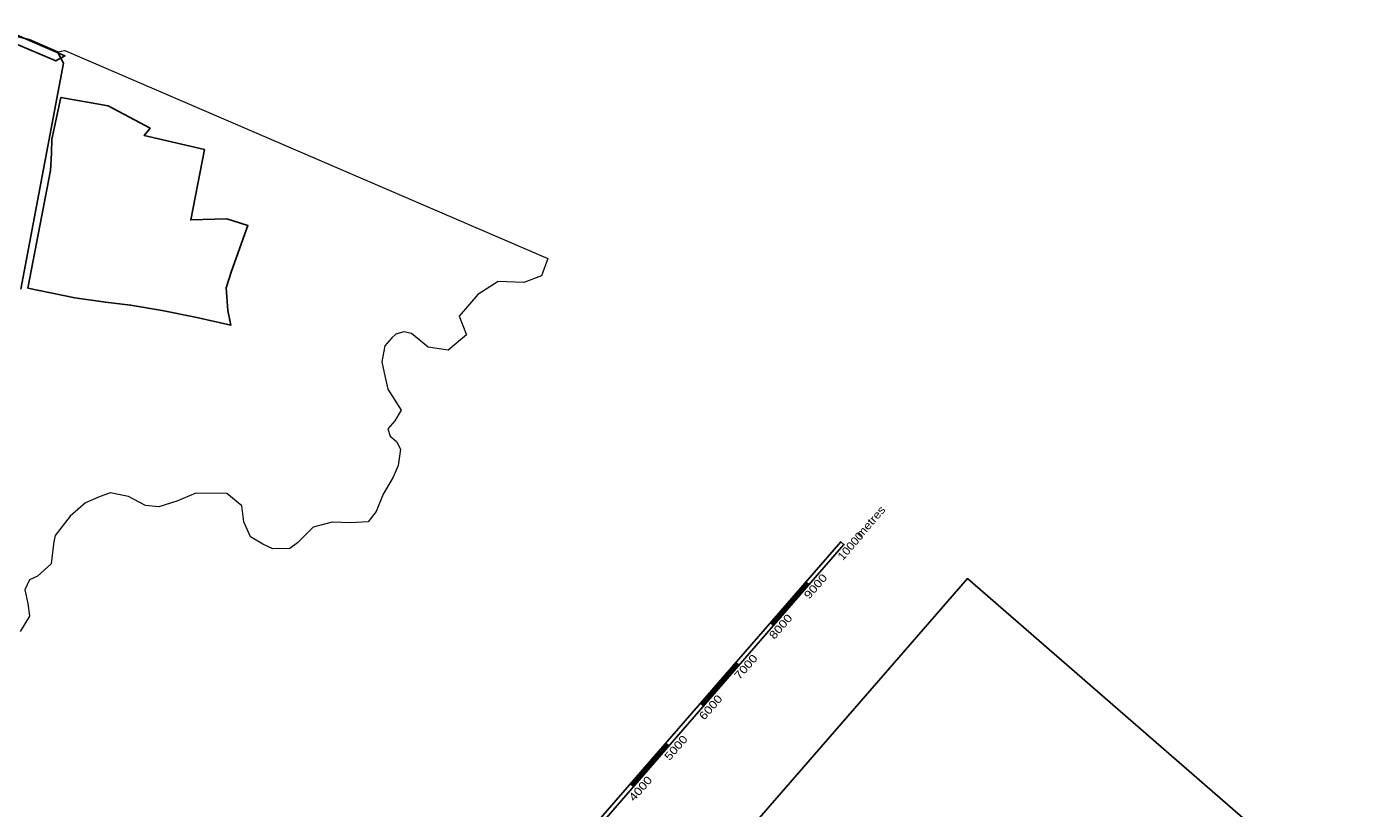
# Model space of a CAD drawing. Extents: x 290038 to 370218, y 2722677 to 2808586.
# Drawn here: x 345284 to 370218, y 2781010 to 2795659 of the extents above; entities that cross this region are included whole.
import ezdxf
from ezdxf.enums import TextEntityAlignment as Align

# ---------------------------------------------------------------- set-up
doc = ezdxf.new("R2010")
doc.units = 0
doc.header["$LTSCALE"] = 88
for name, color, linetype, lineweight in [('20', 7, 'Continuous', 13), ('21', 7, 'Continuous', 25), ('26', 7, 'Continuous', 13), ('63', 7, 'Continuous', 35)]:
    doc.layers.add(name, color=color, linetype=linetype, lineweight=lineweight)

msp = doc.modelspace()

# ---------------------------------------------------------------- linework, layer by layer
at = {"layer": '20', "lineweight": 25}
msp.add_lwpolyline([(313980.4, 2729027.31), (362912.77, 2785317.56), (370218.38, 2778966.9), (321286.01, 2722676.64)], close=True, dxfattribs=at)
at = {"layer": '21'}
msp.add_lwpolyline([(344750.9, 2795557.88), (345329.48, 2795416.12), (345865.2, 2795185.51), (345973.25, 2794976.23), (345177.76, 2790737.42)], dxfattribs=at)
msp.add_lwpolyline([(345304.18, 2790758.67), (345729.85, 2792965.81), (345749.89, 2793288.43), (345754.27, 2793553.08), (345928.31, 2794332.44), (346812.99, 2794171.89), (347598.53, 2793757.49), (347488.87, 2793617.23), (348618.94, 2793353.68), (348361.15, 2792038.63), (349038.19, 2792058.59), (349431.28, 2791931.64), (349120.21, 2791074.54), (349024.14, 2790764.32), (349056.62, 2790342.35), (349109.52, 2790063.71), (348470.63, 2790207.45), (347822.88, 2790341), (347233.43, 2790441.77), (346759.56, 2790495.76), (346189.89, 2790579.34)], close=True, dxfattribs=at)
at = {"layer": '26', "lineweight": 25}
msp.add_lwpolyline([(344723.38, 2795659.4), (346002.04, 2795110.61), (345829.19, 2795017.45), (345037.34, 2795358.32), (344889.26, 2795420.15), (344735.09, 2795470.7), (344699.18, 2795527.53)], close=True, dxfattribs=at)
at = {"layer": '26'}
msp.add_lwpolyline([(345177.76, 2790737.42), (345973.25, 2794976.23), (345865.2, 2795185.51), (345999.51, 2795210.65), (355047.94, 2791315.46), (354934.05, 2790991.89), (354599.89, 2790862.82), (354117.14, 2790881.99), (353739.04, 2790638.55), (353389.67, 2790236.65), (353529.22, 2789886.5), (353183.83, 2789595.56), (352809.31, 2789654.13), (352494.33, 2789908.87), (352352.3, 2789936.98), (352204.11, 2789894.17), (352127.47, 2789827.3), (351995.28, 2789675.22), (351941.21, 2789378.96), (351982.65, 2789171.3), (352049.54, 2788865.23), (352301.7, 2788474.4), (352182.23, 2788273.13), (352050.04, 2788121.06), (352097.65, 2787984.32), (352213.54, 2787883.58), (352291.66, 2787739.38), (352248.13, 2787433.96), (352149.72, 2787214.37), (351966.34, 2786897.02), (351833.45, 2786573.92), (351683.47, 2786380.1), (351353.28, 2786362), (351011.47, 2786373.08), (350655.14, 2786282.35), (350360.24, 2785985.66), (350215.32, 2785882.79), (349894.58, 2785875.55), (349709.31, 2785960.32), (349480.81, 2786101.75), (349355.08, 2786382.68), (349318.7, 2786681.29), (349035.33, 2786908.54), (348452.68, 2786919.2), (348099.64, 2786768.4), (347764.38, 2786659.36), (347511.92, 2786688.11), (347191.88, 2786851.9), (346846.78, 2786923.04), (346630.3, 2786844.24), (346385.5, 2786732.85), (346097.85, 2786487.06), (345816.77, 2786121.15), (345792.81, 2786008.48), (345745.3, 2785592.09), (345487.07, 2785358.88), (345339.97, 2785296.05), (345249.92, 2785107.34), (345304.09, 2784850.48), (345337.19, 2784611.93), (345162.15, 2784325.46)], dxfattribs=at)
at = {"layer": '63', "lineweight": 25}
for p, q in [((353321.51, 2777702.6), (360538.16, 2786004.41)), ((353381.89, 2777650.12), (360598.54, 2785951.92)), ((360606.08, 2785945.36), (360530.61, 2786010.97))]:
    msp.add_line(p, q, dxfattribs=at)
at = {"layer": '63'}
for p, q in [((359237.44, 2784485.09), (359893.5, 2785239.8)), ((359237.81, 2784484.76), (359893.87, 2785239.47)), ((359238.19, 2784484.43), (359894.25, 2785239.14)), ((359238.57, 2784484.1), (359894.63, 2785238.81)), ((359238.95, 2784483.78), (359895, 2785238.48)), ((359239.32, 2784483.45), (359895.38, 2785238.16)), ((359239.7, 2784483.12), (359895.76, 2785237.83)), ((359240.08, 2784482.79), (359896.14, 2785237.5)), ((359240.45, 2784482.46), (359896.51, 2785237.17)), ((359240.83, 2784482.14), (359896.89, 2785236.84)), ((359241.21, 2784481.81), (359897.27, 2785236.52)), ((359241.59, 2784481.48), (359897.65, 2785236.19)), ((359241.97, 2784481.15), (359898.02, 2785235.86)), ((359242.34, 2784480.82), (359898.4, 2785235.53)), ((359242.72, 2784480.5), (359898.78, 2785235.21)), ((359243.1, 2784480.17), (359899.15, 2785234.88)), ((359243.47, 2784479.84), (359899.53, 2785234.55)), ((359243.85, 2784479.51), (359899.91, 2785234.22)), ((359244.23, 2784479.18), (359900.29, 2785233.89)), ((359244.61, 2784478.86), (359900.67, 2785233.56)), ((359244.98, 2784478.53), (359901.04, 2785233.24)), ((359245.36, 2784478.2), (359901.42, 2785232.91)), ((359245.74, 2784477.87), (359901.8, 2785232.58)), ((359246.12, 2784477.54), (359902.17, 2785232.25)), ((359246.49, 2784477.21), (359902.55, 2785231.92)), ((359246.87, 2784476.89), (359902.93, 2785231.6)), ((359247.25, 2784476.56), (359903.31, 2785231.27)), ((359247.62, 2784476.23), (359903.68, 2785230.94)), ((359248, 2784475.9), (359904.06, 2785230.61)), ((359248.38, 2784475.58), (359904.44, 2785230.29)), ((359248.76, 2784475.25), (359904.82, 2785229.96)), ((359249.13, 2784474.92), (359905.19, 2785229.63)), ((359249.51, 2784474.59), (359905.57, 2785229.3)), ((359249.89, 2784474.26), (359905.95, 2785228.97)), ((359250.27, 2784473.94), (359906.32, 2785228.64)), ((359250.64, 2784473.61), (359906.7, 2785228.32)), ((359251.02, 2784473.28), (359907.08, 2785227.99)), ((359251.4, 2784472.95), (359907.46, 2785227.66)), ((359251.78, 2784472.62), (359907.83, 2785227.33)), ((359252.15, 2784472.29), (359908.21, 2785227)), ((359252.53, 2784471.97), (359908.59, 2785226.68)), ((359252.91, 2784471.64), (359908.97, 2785226.35)), ((359253.29, 2784471.31), (359909.34, 2785226.02)), ((359253.66, 2784470.98), (359909.72, 2785225.69)), ((359254.04, 2784470.65), (359910.1, 2785225.36)), ((359254.42, 2784470.33), (359910.48, 2785225.04)), ((359254.79, 2784470), (359910.85, 2785224.71)), ((359255.17, 2784469.67), (359911.23, 2785224.38)), ((359255.55, 2784469.34), (359911.61, 2785224.05)), ((359255.93, 2784469.01), (359911.99, 2785223.72)), ((359256.3, 2784468.69), (359912.36, 2785223.4)), ((359256.68, 2784468.36), (359912.74, 2785223.07)), ((359257.06, 2784468.03), (359913.12, 2785222.74)), ((359257.44, 2784467.7), (359913.49, 2785222.41)), ((359257.81, 2784467.38), (359913.87, 2785222.08)), ((359258.19, 2784467.05), (359914.25, 2785221.75)), ((359258.57, 2784466.72), (359914.63, 2785221.43)), ((359258.95, 2784466.39), (359915, 2785221.1)), ((359259.32, 2784466.06), (359915.38, 2785220.77)), ((359259.7, 2784465.73), (359915.76, 2785220.44)), ((359260.08, 2784465.41), (359916.14, 2785220.12)), ((359260.46, 2784465.08), (359916.51, 2785219.79)), ((359260.83, 2784464.75), (359916.89, 2785219.46)), ((359261.21, 2784464.42), (359917.27, 2785219.13)), ((359261.59, 2784464.09), (359917.65, 2785218.8)), ((359261.96, 2784463.77), (359918.02, 2785218.47)), ((359262.34, 2784463.44), (359918.4, 2785218.15)), ((359262.72, 2784463.11), (359918.78, 2785217.82)), ((359263.1, 2784462.78), (359919.16, 2785217.49)), ((359263.47, 2784462.45), (359919.53, 2785217.16)), ((359263.85, 2784462.13), (359919.91, 2785216.84)), ((359264.23, 2784461.8), (359920.29, 2785216.51)), ((359264.61, 2784461.47), (359920.66, 2785216.18)), ((359264.98, 2784461.14), (359921.04, 2785215.85)), ((359265.36, 2784460.81), (359921.42, 2785215.52)), ((359265.74, 2784460.49), (359921.8, 2785215.19)), ((359266.12, 2784460.16), (359922.17, 2785214.87)), ((359266.49, 2784459.83), (359922.55, 2785214.54)), ((359266.87, 2784459.5), (359922.93, 2785214.21)), ((359267.25, 2784459.17), (359923.31, 2785213.88)), ((359267.63, 2784458.85), (359923.68, 2785213.55)), ((359268, 2784458.52), (359924.06, 2785213.23)), ((359268.38, 2784458.19), (359924.44, 2785212.9)), ((359268.76, 2784457.86), (359924.82, 2785212.57)), ((359269.13, 2784457.53), (359925.19, 2785212.24)), ((359269.51, 2784457.21), (359925.57, 2785211.92)), ((359269.89, 2784456.88), (359925.95, 2785211.59)), ((359270.27, 2784456.55), (359926.33, 2785211.26)), ((359270.64, 2784456.22), (359926.7, 2785210.93)), ((359271.02, 2784455.89), (359927.08, 2785210.6)), ((359271.4, 2784455.57), (359927.46, 2785210.27)), ((359271.78, 2784455.24), (359927.83, 2785209.95)), ((359272.15, 2784454.91), (359928.21, 2785209.62)), ((359272.53, 2784454.58), (359928.59, 2785209.29)), ((359272.91, 2784454.25), (359928.97, 2785208.96)), ((359273.28, 2784453.93), (359929.34, 2785208.63)), ((359273.66, 2784453.6), (359929.72, 2785208.31)), ((359274.04, 2784453.27), (359930.1, 2785207.98)), ((359274.42, 2784452.94), (359930.48, 2785207.65)), ((359274.8, 2784452.61), (359930.85, 2785207.32)), ((357925.45, 2782975.55), (358581.51, 2783730.26)), ((357925.83, 2782975.22), (358581.89, 2783729.93)), ((357926.21, 2782974.89), (358582.27, 2783729.6)), ((357926.59, 2782974.57), (358582.64, 2783729.28)), ((357926.96, 2782974.24), (358583.02, 2783728.95)), ((357927.34, 2782973.91), (358583.4, 2783728.62)), ((357927.72, 2782973.58), (358583.78, 2783728.29)), ((357928.1, 2782973.25), (358584.15, 2783727.96)), ((357928.47, 2782972.93), (358584.53, 2783727.64)), ((357928.85, 2782972.6), (358584.91, 2783727.31)), ((357929.23, 2782972.27), (358585.29, 2783726.98)), ((357929.6, 2782971.94), (358585.66, 2783726.65)), ((357929.98, 2782971.61), (358586.04, 2783726.32)), ((357930.36, 2782971.29), (358586.42, 2783726)), ((357930.74, 2782970.96), (358586.8, 2783725.67)), ((357931.11, 2782970.63), (358587.17, 2783725.34)), ((357931.49, 2782970.3), (358587.55, 2783725.01)), ((357931.87, 2782969.97), (358587.93, 2783724.68)), ((357932.25, 2782969.65), (358588.3, 2783724.35)), ((357932.62, 2782969.32), (358588.68, 2783724.03)), ((357933, 2782968.99), (358589.06, 2783723.7)), ((357933.38, 2782968.66), (358589.44, 2783723.37)), ((357933.76, 2782968.33), (358589.81, 2783723.04)), ((357934.13, 2782968.01), (358590.19, 2783722.71)), ((357934.51, 2782967.68), (358590.57, 2783722.39)), ((357934.89, 2782967.35), (358590.95, 2783722.06)), ((357935.27, 2782967.02), (358591.32, 2783721.73)), ((357935.64, 2782966.69), (358591.7, 2783721.4)), ((357936.02, 2782966.37), (358592.08, 2783721.07)), ((357936.4, 2782966.04), (358592.46, 2783720.75)), ((357936.77, 2782965.71), (358592.83, 2783720.42)), ((357937.15, 2782965.38), (358593.21, 2783720.09)), ((357937.53, 2782965.05), (358593.59, 2783719.76)), ((357937.91, 2782964.73), (358593.97, 2783719.44)), ((357938.28, 2782964.4), (358594.34, 2783719.11)), ((357938.66, 2782964.07), (358594.72, 2783718.78)), ((357939.04, 2782963.74), (358595.1, 2783718.45)), ((357939.42, 2782963.41), (358595.47, 2783718.12)), ((357939.79, 2782963.08), (358595.85, 2783717.79)), ((357940.17, 2782962.76), (358596.23, 2783717.47)), ((357940.55, 2782962.43), (358596.61, 2783717.14)), ((357940.93, 2782962.1), (358596.98, 2783716.81)), ((357941.3, 2782961.77), (358597.36, 2783716.48)), ((357941.68, 2782961.45), (358597.74, 2783716.15)), ((357942.06, 2782961.12), (358598.12, 2783715.83)), ((357942.43, 2782960.79), (358598.49, 2783715.5)), ((357942.81, 2782960.46), (358598.87, 2783715.17)), ((357943.19, 2782960.13), (358599.25, 2783714.84)), ((357943.57, 2782959.8), (358599.63, 2783714.51)), ((357943.94, 2782959.48), (358600, 2783714.19)), ((357944.32, 2782959.15), (358600.38, 2783713.86)), ((357944.7, 2782958.82), (358600.76, 2783713.53)), ((357945.08, 2782958.49), (358601.13, 2783713.2)), ((357945.45, 2782958.17), (358601.51, 2783712.87)), ((357945.83, 2782957.84), (358601.89, 2783712.55)), ((357946.21, 2782957.51), (358602.27, 2783712.22)), ((357946.59, 2782957.18), (358602.64, 2783711.89)), ((357946.96, 2782956.85), (358603.02, 2783711.56)), ((357947.34, 2782956.52), (358603.4, 2783711.23)), ((357947.72, 2782956.2), (358603.78, 2783710.91)), ((357948.1, 2782955.87), (358604.15, 2783710.58)), ((357948.47, 2782955.54), (358604.53, 2783710.25)), ((357948.85, 2782955.21), (358604.91, 2783709.92)), ((357949.23, 2782954.88), (358605.29, 2783709.59)), ((357949.6, 2782954.56), (358605.66, 2783709.27)), ((357949.98, 2782954.23), (358606.04, 2783708.94)), ((357950.36, 2782953.9), (358606.42, 2783708.61)), ((357950.74, 2782953.57), (358606.8, 2783708.28)), ((357951.11, 2782953.25), (358607.17, 2783707.95)), ((357951.49, 2782952.92), (358607.55, 2783707.63)), ((357951.87, 2782952.59), (358607.93, 2783707.3)), ((357952.25, 2782952.26), (358608.3, 2783706.97)), ((357952.62, 2782951.93), (358608.68, 2783706.64)), ((357953, 2782951.6), (358609.06, 2783706.31)), ((357953.38, 2782951.28), (358609.44, 2783705.98)), ((357953.75, 2782950.95), (358609.81, 2783705.66)), ((357954.13, 2782950.62), (358610.19, 2783705.33)), ((357954.51, 2782950.29), (358610.57, 2783705)), ((357954.89, 2782949.96), (358610.95, 2783704.67)), ((357955.27, 2782949.64), (358611.32, 2783704.35)), ((357955.64, 2782949.31), (358611.7, 2783704.02)), ((357956.02, 2782948.98), (358612.08, 2783703.69)), ((357956.4, 2782948.65), (358612.46, 2783703.36)), ((357956.77, 2782948.32), (358612.83, 2783703.03)), ((357957.15, 2782948), (358613.21, 2783702.71)), ((357957.53, 2782947.67), (358613.59, 2783702.38)), ((357957.91, 2782947.34), (358613.96, 2783702.05)), ((357958.28, 2782947.01), (358614.34, 2783701.72)), ((357958.66, 2782946.68), (358614.72, 2783701.39)), ((357959.04, 2782946.36), (358615.1, 2783701.06)), ((357959.42, 2782946.03), (358615.47, 2783700.74)), ((357959.79, 2782945.7), (358615.85, 2783700.41)), ((357960.17, 2782945.37), (358616.23, 2783700.08)), ((357960.55, 2782945.04), (358616.61, 2783699.75)), ((357960.92, 2782944.72), (358616.98, 2783699.42)), ((357961.3, 2782944.39), (358617.36, 2783699.1)), ((357961.68, 2782944.06), (358617.74, 2783698.77)), ((357962.06, 2782943.73), (358618.12, 2783698.44)), ((357962.43, 2782943.4), (358618.49, 2783698.11)), ((357962.81, 2782943.07), (358618.87, 2783697.78)), ((356613.16, 2781466.29), (357269.22, 2782221)), ((356613.53, 2781465.96), (357269.59, 2782220.67)), ((356613.91, 2781465.63), (357269.97, 2782220.34)), ((356614.29, 2781465.3), (357270.35, 2782220.01)), ((356614.67, 2781464.97), (357270.73, 2782219.68)), ((356615.04, 2781464.64), (357271.1, 2782219.35)), ((356615.42, 2781464.32), (357271.48, 2782219.03)), ((356615.8, 2781463.99), (357271.86, 2782218.7)), ((356616.18, 2781463.66), (357272.24, 2782218.37)), ((356616.55, 2781463.33), (357272.61, 2782218.04)), ((356616.93, 2781463), (357272.99, 2782217.71)), ((356617.31, 2781462.68), (357273.37, 2782217.39)), ((356617.69, 2781462.35), (357273.74, 2782217.06)), ((356618.06, 2781462.02), (357274.12, 2782216.73)), ((356618.44, 2781461.69), (357274.5, 2782216.4)), ((356618.82, 2781461.36), (357274.88, 2782216.07)), ((356619.2, 2781461.04), (357275.25, 2782215.75)), ((356619.57, 2781460.71), (357275.63, 2782215.42)), ((356619.95, 2781460.38), (357276.01, 2782215.09)), ((356620.33, 2781460.05), (357276.39, 2782214.76)), ((356620.7, 2781459.72), (357276.76, 2782214.44)), ((356621.08, 2781459.4), (357277.14, 2782214.11)), ((356621.46, 2781459.07), (357277.52, 2782213.78)), ((356621.84, 2781458.74), (357277.9, 2782213.45)), ((356622.21, 2781458.41), (357278.27, 2782213.12)), ((356622.59, 2781458.08), (357278.65, 2782212.79)), ((356622.97, 2781457.76), (357279.03, 2782212.47)), ((356623.35, 2781457.43), (357279.41, 2782212.14)), ((356623.72, 2781457.1), (357279.78, 2782211.81)), ((356624.1, 2781456.77), (357280.16, 2782211.48)), ((356624.48, 2781456.44), (357280.54, 2782211.15)), ((356624.85, 2781456.12), (357280.91, 2782210.83)), ((356625.23, 2781455.79), (357281.29, 2782210.5)), ((356625.61, 2781455.46), (357281.67, 2782210.17)), ((356625.99, 2781455.13), (357282.05, 2782209.84)), ((356626.36, 2781454.8), (357282.42, 2782209.51)), ((356626.74, 2781454.48), (357282.8, 2782209.19)), ((356627.12, 2781454.15), (357283.18, 2782208.86)), ((356627.5, 2781453.82), (357283.56, 2782208.53)), ((356627.87, 2781453.49), (357283.93, 2782208.2)), ((356628.25, 2781453.16), (357284.31, 2782207.87)), ((356628.63, 2781452.84), (357284.69, 2782207.55)), ((356629.01, 2781452.51), (357285.07, 2782207.22)), ((356629.38, 2781452.18), (357285.44, 2782206.89)), ((356629.76, 2781451.85), (357285.82, 2782206.56)), ((356630.14, 2781451.52), (357286.2, 2782206.23)), ((356630.52, 2781451.2), (357286.58, 2782205.91)), ((356630.89, 2781450.87), (357286.95, 2782205.58)), ((356631.27, 2781450.54), (357287.33, 2782205.25)), ((356631.65, 2781450.21), (357287.71, 2782204.92)), ((356632.02, 2781449.88), (357288.08, 2782204.59)), ((356632.4, 2781449.55), (357288.46, 2782204.26)), ((356632.78, 2781449.23), (357288.84, 2782203.94)), ((356633.16, 2781448.9), (357289.22, 2782203.61)), ((356633.53, 2781448.57), (357289.59, 2782203.28)), ((356633.91, 2781448.24), (357289.97, 2782202.95)), ((356634.29, 2781447.92), (357290.35, 2782202.63)), ((356634.67, 2781447.59), (357290.73, 2782202.3)), ((356635.04, 2781447.26), (357291.1, 2782201.97)), ((356635.42, 2781446.93), (357291.48, 2782201.64)), ((356635.8, 2781446.6), (357291.86, 2782201.31)), ((356636.18, 2781446.27), (357292.23, 2782200.98)), ((356636.55, 2781445.95), (357292.61, 2782200.66)), ((356636.93, 2781445.62), (357292.99, 2782200.33)), ((356637.31, 2781445.29), (357293.37, 2782200)), ((356637.69, 2781444.96), (357293.75, 2782199.67)), ((356638.06, 2781444.63), (357294.12, 2782199.35)), ((356638.44, 2781444.31), (357294.5, 2782199.02)), ((356638.82, 2781443.98), (357294.88, 2782198.69)), ((356639.19, 2781443.65), (357295.25, 2782198.36)), ((356639.57, 2781443.32), (357295.63, 2782198.03)), ((356639.95, 2781443), (357296.01, 2782197.71)), ((356640.33, 2781442.67), (357296.39, 2782197.38)), ((356640.7, 2781442.34), (357296.76, 2782197.05)), ((356641.08, 2781442.01), (357297.14, 2782196.72)), ((356641.46, 2781441.68), (357297.52, 2782196.39)), ((356641.84, 2781441.35), (357297.9, 2782196.06)), ((356642.21, 2781441.03), (357298.27, 2782195.74)), ((356642.59, 2781440.7), (357298.65, 2782195.41)), ((356642.97, 2781440.37), (357299.03, 2782195.08)), ((356643.35, 2781440.04), (357299.4, 2782194.75)), ((356643.72, 2781439.71), (357299.78, 2782194.42)), ((356644.1, 2781439.39), (357300.16, 2782194.1)), ((356644.48, 2781439.06), (357300.54, 2782193.77)), ((356644.86, 2781438.73), (357300.92, 2782193.44)), ((356645.23, 2781438.4), (357301.29, 2782193.11)), ((356645.61, 2781438.07), (357301.67, 2782192.78)), ((356645.99, 2781437.75), (357302.05, 2782192.46)), ((356646.36, 2781437.42), (357302.42, 2782192.13)), ((356646.74, 2781437.09), (357302.8, 2782191.8)), ((356647.12, 2781436.76), (357303.18, 2782191.47)), ((356647.5, 2781436.44), (357303.56, 2782191.15)), ((356647.87, 2781436.11), (357303.93, 2782190.82)), ((356648.25, 2781435.78), (357304.31, 2782190.49)), ((356648.63, 2781435.45), (357304.69, 2782190.16)), ((356649.01, 2781435.12), (357305.07, 2782189.83)), ((356649.38, 2781434.79), (357305.44, 2782189.5)), ((356649.76, 2781434.47), (357305.82, 2782189.18)), ((356650.14, 2781434.14), (357306.2, 2782188.85)), ((356650.52, 2781433.81), (357306.57, 2782188.52))]:
    msp.add_line(p, q, dxfattribs=at)
at = {"layer": '63', "lineweight": 13}
for p, q in [((359950.03, 2785190.65), (359874.56, 2785256.26)), ((359293.96, 2784435.95), (359218.5, 2784501.55)), ((358637.9, 2783681.24), (358562.44, 2783746.84)), ((357981.84, 2782926.53), (357906.38, 2782992.13)), ((357325.78, 2782171.82), (357250.32, 2782237.42)), ((356669.73, 2781417.11), (356594.26, 2781482.71))]:
    msp.add_line(p, q, dxfattribs=at)
at = {"layer": '63'}
for points in [[(359275.1, 2784452.35), (359931.16, 2785207.06), (359893.42, 2785239.86), (359237.37, 2784485.15)], [(358581.31, 2783730.44), (357925.25, 2782975.73), (357962.98, 2782942.93), (358619.04, 2783697.64)], [(356650.86, 2781433.51), (357306.92, 2782188.22), (357269.19, 2782221.02), (356613.13, 2781466.31)]]:
    msp.add_lwpolyline(points, close=True, dxfattribs=at)

# ---------------------------------------------------------------- texts
for s, width, p in [('metres', 1.15, (361155.19, 2786331.35)), ('10000', 1.1, (360778.34, 2785877.68)), ('9000', 1.2, (360122.28, 2785122.97)), ('8000', 1.2, (359468.96, 2784368.19)), ('7000', 1.2, (358817.17, 2783613.57)), ('6000', 1.2, (358157.88, 2782855.14)), ('5000', 1.2, (357507.13, 2782097.31)), ('4000', 1.2, (356841.88, 2781332.03))]:
    msp.add_text(s, height=150, rotation=49, dxfattribs=dict(at, width=width)).set_placement(p, align=Align.CENTER)

doc.saveas('drawing.dxf')
